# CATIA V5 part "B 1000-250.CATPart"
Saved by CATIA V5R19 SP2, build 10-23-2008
Part number: B 1000-250
Bounding box of the stored display mesh (mm): x -24.865 to 24.865, y -24.997 to 24.997, z 0 to 595
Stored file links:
  C:\Users\Bora\Desktop\3D Katı model\B serisi\B 1000\B 1000-250.CATPart
  C:\Program Files\Dassault Systemes\B19\intel_a\reffiles\standard\MetricThickPitch.txt
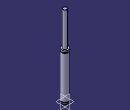
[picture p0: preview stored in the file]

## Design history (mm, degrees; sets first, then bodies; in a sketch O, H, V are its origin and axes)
Body1 (main body)
  Sketch1 on yz-plane, origin (0, 0, 0), H (0, 1, 0), V (0, 0, 1)
    point P1 (25, 329.5)
    point P2 (25, 325.5)
    point P3 (25, 329.5)
    point P6 (25, 325.5)
    point P9 (15, 594)
    point P11 (15, 594)
    arc A1 centre (25, 327.5) radius 2 from (25, 329.5) to (25, 325.5) ccw
    line L1 (25, 329.5) -> (25, 342)
    line L2 (25, 13) -> (25, 325.5)
    line L3 (21.5, 13) -> (21.5, 8)
    arc A2 centre (14, 594) radius 1 from (15, 594) to (14, 595) ccw
    line L4 (15, 594) -> (15, 342)
    line L5 (25, 0) -> (25, 8)
    line L6 (14, 595) -> (0, 595)
    point P15 (0, 595)
    line L7 (15, 342) -> (25, 342)
    line L8 (0, 0) -> (25, 0)
    line L9 (21.5, 8) -> (25, 8)
    line L10 (21.5, 13) -> (25, 13)
    coincidence: P15 V, P1 P3, P2 P6, P9 P11
    tangency: L6 A2
    horizontal: L7 H, L8 H, L9 H, L10 H
  Shaft1: profile Sketch1, axis Sketch1.V, angle 360
  Sketch2 on face of Shaft1 from Sketch1.L8, origin (0, 0, 0), H (1, 0, 0), V (0, -1, 0)
    point P1 (10, 0)
    distance P1 V = 10
  Hole1: placed by Sketch2, at (10, 0, 0) direction (0, 0, 1), diameter 6.647, depth 13, threaded "M8", thread diameter 8, thread depth 13, pitch 1.25
  CircPattern1: of Hole1, instances 2, angular step 180, axis from xy-plane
